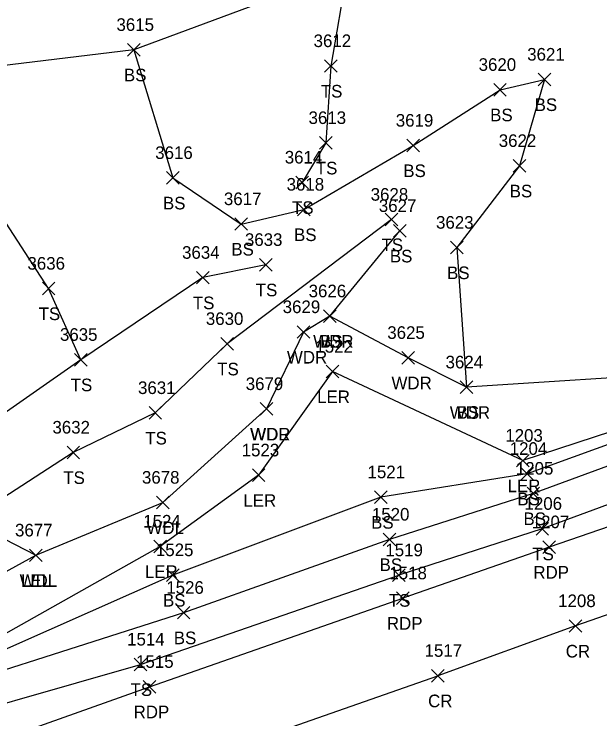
# Model space of a CAD drawing. Extents: x 1599569 to 1610055, y 642560 to 647860.
# Drawn here: x 1601916 to 1602008.8, y 647394 to 647505.8 of the extents above; entities that cross this region are included whole.
import ezdxf

# ---------------------------------------------------------------- set-up
doc = ezdxf.new("R2010")
doc.units = 0
for name, color, linetype in [('L_A', 7, 'Continuous'), ('L_I', 7, 'Continuous'), ('L_TIC', 7, 'Continuous'), ('LARO', 7, 'Continuous'), ('LAWA', 7, 'Continuous'), ('LELB', 7, 'Continuous'), ('LSOGP', 7, 'Continuous'), ('P_A', 7, 'Continuous'), ('P_I', 7, 'Continuous'), ('P_TIC', 7, 'Continuous'), ('PET', 7, 'Continuous'), ('PRC', 7, 'Continuous')]:
    doc.layers.add(name, color=color, linetype=linetype)

msp = doc.modelspace()

# ---------------------------------------------------------------- linework, layer by layer
at = {"layer": 'L_TIC'}
for points in [[(1601933.95, 647499.11), (1601935.95, 647501.11)], [(1601935.95, 647499.11), (1601933.95, 647501.11)], [(1601965.2, 647496.54), (1601967.2, 647498.54)], [(1601967.2, 647496.54), (1601965.2, 647498.54)], [(1601999.06, 647494.4), (1602001.06, 647496.4)], [(1602001.06, 647494.4), (1601999.06, 647496.4)], [(1601992.01, 647492.77), (1601994.01, 647494.77)], [(1601994.01, 647492.77), (1601992.01, 647494.77)], [(1601964.4, 647484.34), (1601966.4, 647486.34)], [(1601966.4, 647484.34), (1601964.4, 647486.34)], [(1601978.24, 647483.92), (1601980.24, 647485.92)], [(1601980.24, 647483.92), (1601978.24, 647485.92)], [(1601995.11, 647480.7), (1601997.11, 647482.7)], [(1601997.11, 647480.7), (1601995.11, 647482.7)], [(1601940.14, 647478.79), (1601942.14, 647480.79)], [(1601942.14, 647478.79), (1601940.14, 647480.79)], [(1601960.63, 647478.07), (1601962.63, 647480.07)], [(1601962.63, 647478.07), (1601960.63, 647480.07)], [(1601960.92, 647473.77), (1601962.92, 647475.77)], [(1601962.92, 647473.77), (1601960.92, 647475.77)], [(1601950.98, 647471.47), (1601952.98, 647473.47)], [(1601952.98, 647471.47), (1601950.98, 647473.47)], [(1601974.82, 647472.17), (1601976.82, 647474.17)], [(1601976.82, 647472.17), (1601974.82, 647474.17)], [(1601976.11, 647470.38), (1601978.11, 647472.38)], [(1601978.11, 647470.38), (1601976.11, 647472.38)], [(1601985.18, 647467.73), (1601987.18, 647469.73)], [(1601987.18, 647467.73), (1601985.18, 647469.73)], [(1601954.88, 647465), (1601956.88, 647467)], [(1601956.88, 647465), (1601954.88, 647467)], [(1601944.91, 647462.96), (1601946.91, 647464.96)], [(1601946.91, 647462.96), (1601944.91, 647464.96)], [(1601920.46, 647461.23), (1601922.46, 647463.23)], [(1601922.46, 647461.23), (1601920.46, 647463.23)], [(1601965.03, 647456.85), (1601967.03, 647458.85)], [(1601967.03, 647456.85), (1601965.03, 647458.85)], [(1601965.03, 647456.85), (1601967.03, 647458.85)], [(1601967.03, 647456.85), (1601965.03, 647458.85)], [(1601960.87, 647454.34), (1601962.87, 647456.34)], [(1601962.87, 647454.34), (1601960.87, 647456.34)], [(1601948.77, 647452.46), (1601950.77, 647454.46)], [(1601950.77, 647452.46), (1601948.77, 647454.46)], [(1601925.55, 647449.94), (1601927.55, 647451.94)], [(1601927.55, 647449.94), (1601925.55, 647451.94)], [(1601925.55, 647449.94), (1601927.55, 647451.94)], [(1601927.55, 647449.94), (1601925.55, 647451.94)], [(1601977.44, 647450.25), (1601979.44, 647452.25)], [(1601979.44, 647450.25), (1601977.44, 647452.25)], [(1601965.44, 647448.06), (1601967.44, 647450.06)], [(1601967.44, 647448.06), (1601965.44, 647450.06)], [(1601986.69, 647445.57), (1601988.69, 647447.57)], [(1601988.69, 647445.57), (1601986.69, 647447.57)], [(1601986.69, 647445.57), (1601988.69, 647447.57)], [(1601988.69, 647445.57), (1601986.69, 647447.57)], [(1601955.01, 647442.13), (1601957.01, 647444.13)], [(1601957.01, 647442.13), (1601955.01, 647444.13)], [(1601955.01, 647442.13), (1601957.01, 647444.13)], [(1601957.01, 647442.13), (1601955.01, 647444.13)], [(1601937.37, 647441.5), (1601939.37, 647443.5)], [(1601939.37, 647441.5), (1601937.37, 647443.5)], [(1601924.37, 647435.23), (1601926.37, 647437.23)], [(1601926.37, 647435.23), (1601924.37, 647437.23)], [(1601995.63, 647433.93), (1601997.63, 647435.93)], [(1601997.63, 647433.93), (1601995.63, 647435.93)], [(1601953.75, 647431.61), (1601955.75, 647433.61)], [(1601955.75, 647431.61), (1601953.75, 647433.61)], [(1601996.32, 647431.85), (1601998.32, 647433.85)], [(1601998.32, 647431.85), (1601996.32, 647433.85)], [(1601997.29, 647428.71), (1601999.29, 647430.71)], [(1601999.29, 647428.71), (1601997.29, 647430.71)], [(1601973.14, 647428.14), (1601975.14, 647430.14)], [(1601975.14, 647428.14), (1601973.14, 647430.14)], [(1601938.56, 647427.28), (1601940.56, 647429.28)], [(1601940.56, 647427.28), (1601938.56, 647429.28)], [(1601998.72, 647423.13), (1602000.72, 647425.13)], [(1602000.72, 647423.13), (1601998.72, 647425.13)], [(1601974.48, 647421.42), (1601976.48, 647423.42)], [(1601976.48, 647421.42), (1601974.48, 647423.42)], [(1601938.14, 647420.32), (1601940.14, 647422.32)], [(1601940.14, 647420.32), (1601938.14, 647422.32)], [(1601918.44, 647418.91), (1601920.44, 647420.91)], [(1601920.44, 647418.91), (1601918.44, 647420.91)], [(1601918.44, 647418.91), (1601920.44, 647420.91)], [(1601920.44, 647418.91), (1601918.44, 647420.91)], [(1601940.15, 647415.78), (1601942.15, 647417.78)], [(1601942.15, 647415.78), (1601940.15, 647417.78)], [(1601975.97, 647415.76), (1601977.97, 647417.76)], [(1601977.97, 647415.76), (1601975.97, 647417.76)], [(1601975.97, 647415.76), (1601977.97, 647417.76)], [(1601977.97, 647415.76), (1601975.97, 647417.76)], [(1601941.86, 647409.81), (1601943.86, 647411.81)], [(1601943.86, 647409.81), (1601941.86, 647411.81)], [(1601935.03, 647401.6), (1601937.03, 647403.6)], [(1601937.03, 647401.6), (1601935.03, 647403.6)]]:
    msp.add_lwpolyline(points, dxfattribs=at)
at = {"layer": 'LARO'}
for points in [[(1602281.17, 647528.1), (1602249.28, 647518.68), (1602215.29, 647506.81), (1602182.96, 647503.09), (1602138.81, 647485.94), (1602110.91, 647474.13), (1602102.89, 647472.66), (1602065.84, 647459), (1602030.57, 647446.06), (1601996.63, 647434.93), (1601966.44, 647449.06), (1601954.75, 647432.61), (1601939.14, 647421.32), (1601907.5, 647403.47), (1601898.14, 647399.78), (1601888.11, 647399.67), (1601874.07, 647394.79), (1601848.49, 647386.96)], [(1601876.5, 647404.44), (1601888.35, 647407.56), (1601897.7, 647420.74), (1601909.43, 647425.08), (1601919.44, 647419.91)]]:
    msp.add_lwpolyline(points, dxfattribs=at)
at = {"layer": 'LAWA'}
for points in [[(1602091.27, 647476.65), (1602071.28, 647471.64), (1602066.04, 647466.69), (1602056.34, 647458.19), (1602049.66, 647457.08), (1602043.71, 647455.77), (1602038.34, 647457.7), (1602031, 647453.39), (1602023.77, 647448.94), (1601987.69, 647446.57), (1601978.44, 647451.25), (1601966.03, 647457.85), (1601961.87, 647455.34), (1601956.01, 647443.13)], [(1601867.97, 647400.47), (1601875.33, 647398.31), (1601888.86, 647404.16), (1601900.83, 647409.72), (1601919.44, 647419.91), (1601939.56, 647428.28), (1601956.01, 647443.13)]]:
    msp.add_lwpolyline(points, dxfattribs=at)
at = {"layer": 'LELB'}
for points in [[(1602023.77, 647448.94), (1602012.78, 647461.5), (1602018.04, 647475.49), (1602031.09, 647508.58), (1602032.84, 647522.18), (1601985.71, 647530.93), (1601968.77, 647512.71), (1601966.2, 647497.54), (1601965.4, 647485.34), (1601961.63, 647479.07)], [(1602281.75, 647527.04), (1602249.8, 647516.84), (1602215.67, 647505.92), (1602184.38, 647497.32), (1602140.31, 647484.48), (1602111.03, 647472.46), (1602103.56, 647472.02), (1602066.93, 647456.96), (1602030.71, 647444.95), (1601997.32, 647432.85), (1601974.14, 647429.14), (1601941.15, 647416.78), (1601908.35, 647402.2), (1601898.71, 647398.5), (1601889.19, 647398.4), (1601875.8, 647390.82), (1601849.76, 647382.4), (1601821.01, 647371.25), (1601793.34, 647364.77), (1601777.94, 647362.34), (1601752.2, 647359.53), (1601736.48, 647357.95), (1601705.98, 647345.02)], [(1602280.55, 647523.47), (1602249.62, 647512.84), (1602216.53, 647503.11), (1602185.17, 647491.71), (1602142.18, 647479.3), (1602111.48, 647470.2), (1602106.19, 647468.46), (1602102.05, 647467.18), (1602101.62, 647468.1), (1602067.36, 647454.23), (1602033.18, 647442.57), (1601998.29, 647429.71), (1601975.48, 647422.42), (1601942.86, 647410.81), (1601909.09, 647400.02), (1601898.83, 647395.63), (1601887.98, 647393.87), (1601875.49, 647387.75), (1601851.11, 647380.46), (1601821.5, 647369.32), (1601787.55, 647360.24), (1601760.01, 647349.17)], [(1602281.6, 647518.52), (1602249.84, 647509.15), (1602217.8, 647500.07), (1602186.45, 647487.37), (1602145.36, 647474.12), (1602111.07, 647462.86), (1602069.25, 647448.56), (1602037.69, 647438.14), (1601999.72, 647424.13), (1601976.97, 647416.76)], [(1601934.95, 647500.11), (1601941.14, 647479.79), (1601951.98, 647472.47), (1601961.92, 647474.77), (1601979.24, 647484.92), (1601993.01, 647493.77), (1602000.06, 647495.4), (1601996.11, 647481.7), (1601986.18, 647468.73), (1601987.69, 647446.57)], [(1601926.55, 647450.94), (1601921.46, 647462.23), (1601910.97, 647478.31), (1601911.79, 647497.33)], [(1601975.82, 647473.17), (1601949.77, 647453.46), (1601938.37, 647442.5), (1601925.37, 647436.23), (1601912.2, 647427.69), (1601900.33, 647428.06), (1601896.41, 647423.4), (1601887.97, 647418.71), (1601878.75, 647407.34), (1601867.97, 647400.47), (1601856.37, 647399.57)], [(1601966.03, 647457.85), (1601977.11, 647471.38)], [(1601955.88, 647466), (1601945.91, 647463.96), (1601926.55, 647450.94), (1601903.31, 647434.7), (1601900.33, 647428.06)], [(1601770.52, 647348.15), (1601798.65, 647357.36), (1601836.31, 647369.34), (1601855.09, 647377.48), (1601895.73, 647391.04), (1601936.03, 647402.6), (1601976.97, 647416.76)]]:
    msp.add_lwpolyline(points, dxfattribs=at)
at = {"layer": 'LSOGP'}
msp.add_lwpolyline([(1602270.92, 647573.59), (1602244.07, 647576.21), (1602237.28, 647573.92), (1602217.11, 647567.37), (1602192.53, 647561.45), (1602183.25, 647563.11), (1602161.74, 647558.96), (1602144.11, 647557.08), (1602126.59, 647554.38), (1602107.84, 647548.42), (1602095.81, 647542.98), (1602073.68, 647537.86), (1602060.94, 647529.13), (1602032.84, 647522.18), (1601985.71, 647530.93), (1601968.77, 647512.71), (1601934.95, 647500.1), (1601911.8, 647497.32)], dxfattribs=at)
at = {"layer": 'P_TIC'}
for points in [[(1601999.82, 647420.21), (1602001.82, 647422.21)], [(1602001.82, 647420.21), (1601999.82, 647422.21)], [(1601976.59, 647412.11), (1601978.59, 647414.11)], [(1601978.59, 647412.11), (1601976.59, 647414.11)], [(1601976.59, 647412.11), (1601978.59, 647414.11)], [(1601978.59, 647412.11), (1601976.59, 647414.11)], [(1602004, 647407.7), (1602006, 647409.7)], [(1602006, 647407.7), (1602004, 647409.7)], [(1601982.17, 647399.81), (1601984.17, 647401.81)], [(1601984.17, 647399.81), (1601982.17, 647401.81)], [(1601982.17, 647399.81), (1601984.17, 647401.81)], [(1601984.17, 647399.81), (1601982.17, 647401.81)], [(1601936.45, 647398.06), (1601938.45, 647400.06)], [(1601938.45, 647398.06), (1601936.45, 647400.06)]]:
    msp.add_lwpolyline(points, dxfattribs=at)
at = {"layer": 'PET'}
for points in [[(1602282.38, 647515.6), (1602249.91, 647506.25), (1602218.97, 647495.88), (1602186.79, 647485), (1602146.11, 647471.1), (1602112.18, 647459.69), (1602070.34, 647445.01), (1602039.17, 647434.41), (1602000.82, 647421.21), (1601977.59, 647413.11)], [(1601897.73, 647384.95), (1601937.45, 647399.06), (1601977.59, 647413.11)]]:
    msp.add_lwpolyline(points, dxfattribs=at)
at = {"layer": 'PRC'}
for points in [[(1602285.69, 647502.77), (1602253.57, 647492.91), (1602223.2, 647483.2), (1602189.65, 647471.74), (1602149.63, 647458.23), (1602115.56, 647446.97), (1602074.55, 647432.6), (1602043.17, 647422.05), (1602005, 647408.7), (1601983.17, 647400.81)], [(1601770.61, 647326.17), (1601806.22, 647338.1), (1601841.23, 647350.27), (1601863.46, 647358.2), (1601902.17, 647372.01), (1601941.02, 647386.06), (1601983.17, 647400.81)]]:
    msp.add_lwpolyline(points, dxfattribs=at)

# ---------------------------------------------------------------- texts
at = {"layer": 'L_A'}
for s, p in [('BS', (1601933.39, 647495.11)), ('TS', (1601964.61, 647492.54)), ('BS', (1601998.5, 647490.4)), ('BS', (1601991.45, 647488.77)), ('TS', (1601963.81, 647480.34)), ('BS', (1601977.68, 647479.92)), ('BS', (1601994.55, 647476.7)), ('BS', (1601939.58, 647474.79)), ('TS', (1601960.04, 647474.07)), ('BS', (1601960.36, 647469.77)), ('TS', (1601974.23, 647468.17)), ('BS', (1601950.42, 647467.47)), ('BS', (1601975.55, 647466.38)), ('BS', (1601984.62, 647463.73)), ('TS', (1601954.29, 647461)), ('TS', (1601944.32, 647458.96)), ('TS', (1601919.87, 647457.23)), ('WDR', (1601963.4, 647452.85)), ('BS', (1601964.47, 647452.85)), ('WDR', (1601959.23, 647450.34)), ('TS', (1601948.18, 647448.46)), ('TS', (1601924.96, 647445.94)), ('TS', (1601924.96, 647445.94)), ('WDR', (1601975.81, 647446.25)), ('LER', (1601964.02, 647444.06)), ('WDR', (1601985.05, 647441.57)), ('BS', (1601986.13, 647441.57)), ('WDR', (1601953.38, 647438.13)), ('WDL', (1601953.43, 647438.13)), ('TS', (1601936.78, 647437.5)), ('TS', (1601923.78, 647431.23)), ('LER', (1601994.21, 647429.93)), ('LER', (1601952.33, 647427.61)), ('BS', (1601995.76, 647427.85)), ('BS', (1601996.73, 647424.71)), ('WDL', (1601936.97, 647423.28)), ('BS', (1601972.58, 647424.14)), ('TS', (1601998.13, 647419.13)), ('BS', (1601973.92, 647417.42)), ('LER', (1601936.72, 647416.32)), ('WDL', (1601916.86, 647414.91)), ('LEL', (1601917.08, 647414.91)), ('BS', (1601939.59, 647411.78)), ('TS', (1601975.38, 647411.76)), ('TS', (1601975.38, 647411.76)), ('BS', (1601941.3, 647405.81)), ('TS', (1601934.44, 647397.6))]:
    msp.add_text(s, height=2, dxfattribs=at).set_placement(p)
at = {"layer": 'L_I'}
for s, p in [('3615', (1601932.21, 647503.11)), ('3612', (1601963.46, 647500.54)), ('3621', (1601997.32, 647498.4)), ('3620', (1601989.62, 647496.77)), ('3613', (1601962.66, 647488.34)), ('3619', (1601976.49, 647487.92)), ('3622', (1601992.81, 647484.7)), ('3616', (1601938.35, 647482.79)), ('3614', (1601958.89, 647482.07)), ('3618', (1601959.18, 647477.77)), ('3628', (1601972.51, 647476.17)), ('3617', (1601949.24, 647475.47)), ('3627', (1601973.8, 647474.38)), ('3623', (1601982.87, 647471.73)), ('3633', (1601952.57, 647469)), ('3634', (1601942.61, 647466.96)), ('3636', (1601918.1, 647465.23)), ('3626', (1601962.67, 647460.85)), ('3626', (1601962.67, 647460.85)), ('3629', (1601958.56, 647458.34)), ('3630', (1601946.38, 647456.46)), ('3635', (1601923.25, 647453.94)), ('3635', (1601923.25, 647453.94)), ('3625', (1601975.14, 647454.25)), ('1522', (1601963.75, 647452.06)), ('3624', (1601984.38, 647449.57)), ('3624', (1601984.38, 647449.57)), ('3631', (1601935.63, 647445.5)), ('3679', (1601952.7, 647446.13)), ('3679', (1601952.7, 647446.13)), ('3632', (1601922.06, 647439.23)), ('1203', (1601993.85, 647437.93)), ('1523', (1601952.06, 647435.61)), ('1204', (1601994.55, 647435.85)), ('1521', (1601972.01, 647432.14)), ('1205', (1601995.52, 647432.71)), ('3678', (1601936.25, 647431.28)), ('1206', (1601996.9, 647427.13)), ('1520', (1601972.7, 647425.42)), ('1524', (1601936.45, 647424.32)), ('3677', (1601916.13, 647422.91)), ('3677', (1601916.13, 647422.91)), ('1525', (1601938.46, 647419.78)), ('1519', (1601974.84, 647419.76)), ('1519', (1601974.84, 647419.76)), ('1526', (1601940.11, 647413.81)), ('1514', (1601933.9, 647405.6))]:
    msp.add_text(s, height=2, dxfattribs=at).set_placement(p)
at = {"layer": 'P_A'}
for s, p in [('RDP', (1601998.3, 647416.21)), ('RDP', (1601975.08, 647408.11)), ('RDP', (1601975.08, 647408.11)), ('CR', (1602003.43, 647403.7)), ('CR', (1601981.61, 647395.81)), ('CR', (1601981.61, 647395.81)), ('RDP', (1601934.93, 647394.06))]:
    msp.add_text(s, height=2, dxfattribs=at).set_placement(p)
at = {"layer": 'P_I'}
for s, p in [('1207', (1601998.04, 647424.21)), ('1518', (1601975.47, 647416.11)), ('1518', (1601975.47, 647416.11)), ('1208', (1602002.23, 647411.7)), ('1517', (1601981.05, 647403.81)), ('1517', (1601981.05, 647403.81)), ('1515', (1601935.32, 647402.06))]:
    msp.add_text(s, height=2, dxfattribs=at).set_placement(p)

doc.saveas('drawing.dxf')
